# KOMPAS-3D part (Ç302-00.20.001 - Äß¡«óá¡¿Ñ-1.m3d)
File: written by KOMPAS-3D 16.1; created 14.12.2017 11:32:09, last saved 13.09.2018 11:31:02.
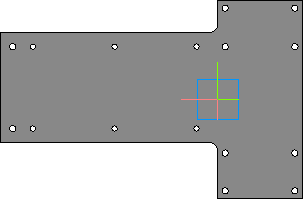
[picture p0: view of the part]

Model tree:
1. Эскиз:1
2. Операция выдавливания:1
     Расстояние 1 = 8
3. Эскиз:4
4. Вырезать элемент выдавливания:2
     Расстояние 1 = 8
5. Массив по сетке:1  (with: Вырезать элемент выдавливания:2, Эскиз:4)  (2 pattern instances)
     Наклон = 90; Шаг 1 = 100; Угол раствора = 90; Номер 1 = 1
6. Эскиз:5
7. Операция выдавливания:2
     Расстояние 1 = 144.5; Расстояние 2 = 8
8. Эскиз:6
9. Вырезать элемент выдавливания:3
     Расстояние 1 = 8
10. Эскиз:8
11. Вырезать элемент выдавливания:4
     Расстояние 1 = 8
12. Массив по сетке:2  (with: Вырезать элемент выдавливания:4, Эскиз:8)  (3 pattern instances)
     Шаг 1 = 100; Угол раствора = 90; Номер 1 = 1
13. Скругление:2
     Радиус = 10
14. Эскиз:7
15. Операция выдавливания:3
     Расстояние 1 = 144.5; Расстояние 2 = 15
16. Скругление:1
     Радиус = 10
17. Фаска:2
     Угол = 45; Длина 1 = 1; Длина 2 = 1
18. Эскиз:2
19. Отверстие:1
     Глубина выреза = 15; Диаметр отверстия = 6; Угол конуса торца = 118; Координата X = -95; Координата Y = 12; Диаметр цековки/зенковки = 7.6; Глубина цековки = 8; Угол зенковки = 90
20. Эскиз:3
21. Вырезать элемент выдавливания:1
     Расстояние 1 = 15
22. Средняя плоскость:1
23. Зеркальный массив:1
24. Экземпляр ( 1 )
25. Экземпляр ( 2 )  (with: Вырезать элемент выдавливания:1)  (labels: А302-00.20.001; Сталь 20  ГОСТ 1050-2013)

Expressions: 26+3; 250+16
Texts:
  Body Specification ( left align )
  Body Specificaton ( centered )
